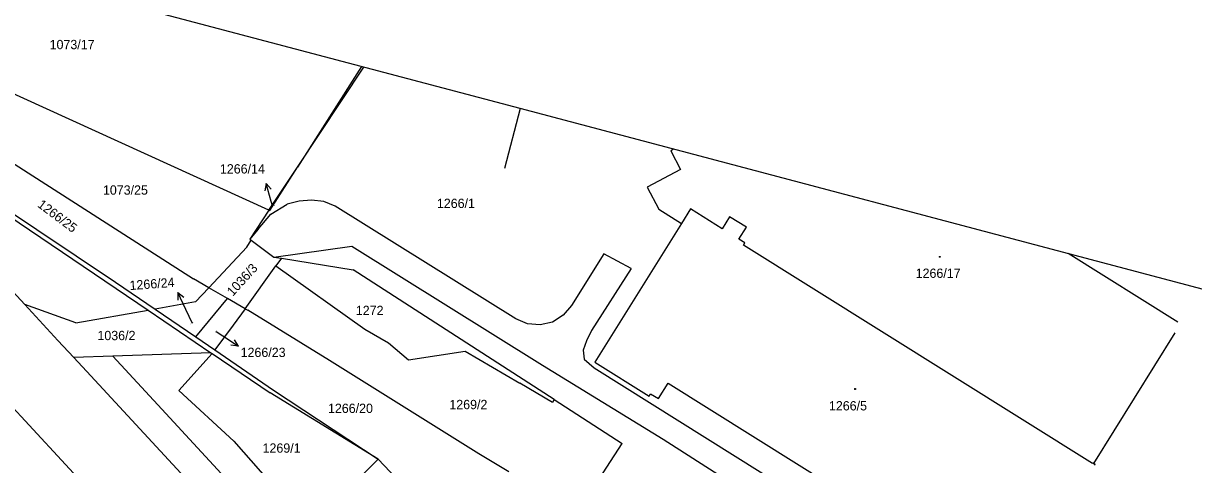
# Model space of a CAD drawing. Extents: x -805011 to -803920, y -1150790 to -1150234.
# Drawn here: x -804203.4 to -804014.7, y -1150506.7 to -1150435.6 of the extents above; entities that cross this region are included whole.
import ezdxf

# ---------------------------------------------------------------- set-up
doc = ezdxf.new("R2010")
doc.units = 0
for name, color, linetype in [('Default', 7, 'Continuous'), ('formát', 7, 'Continuous'), ('kn_celek - Cisla parcel pomocna', 7, 'Continuous'), ('kn_celek - Cisla pozemkovych parcel', 7, 'Continuous'), ('kn_celek - Cisla stavebnich parcel', 7, 'Continuous'), ('kn_celek - Hranice parcel', 7, 'Continuous'), ('kn_celek - Znacky budov', 7, 'Continuous')]:
    doc.layers.add(name, color=color, linetype=linetype)

# ---------------------------------------------------------------- blocks, each defined once
blk = doc.blocks.new('402')
at = {"layer": 'Default'}
for p, q in [((-0.8, 0.8), (0.7, 0.8)), ((-0.8, 0.8), (-0.8, -0.7)), ((0.7, 0.8), (0.7, -0.7)), ((0.7, -0.7), (-0.8, -0.7))]:
    blk.add_line(p, q, dxfattribs=at)
blk = doc.blocks.new('Z61')
at = {"layer": 'Default'}
for p, q in [((0, 0), (30, 0)), ((30, 0), (19.2, 5.3)), ((30, 0), (19.2, -5.3))]:
    blk.add_line(p, q, dxfattribs=at)

msp = doc.modelspace()

# ---------------------------------------------------------------- linework, layer by layer
at = {"layer": 'formát'}
for p, q in [((-804123.29, -1150449.3), (-804326.3, -1150395.58)), ((-804123.29, -1150449.3), (-804125.85, -1150458.97)), ((-803920.28, -1150503.02), (-804123.29, -1150449.3))]:
    msp.add_line(p, q, dxfattribs=at)
at = {"layer": 'kn_celek - Cisla parcel pomocna'}
for p, q in [((-804163.26, -1150464.96), (-804163.46, -1150464.27)), ((-804176.17, -1150483.96), (-804177.24, -1150481.68)), ((-804172.33, -1150485.22), (-804171.25, -1150485.95))]:
    msp.add_line(p, q, dxfattribs=at)
at = {"layer": 'kn_celek - Hranice parcel'}
for p, q in [((-804148.92, -1150442.52), (-804159.21, -1150458.72)), ((-804159.21, -1150458.72), (-804148.5, -1150442.63)), ((-804163.83, -1150465.67), (-804208.87, -1150445.2)), ((-804213.63, -1150452.62), (-804176.02, -1150476.77)), ((-804098.56, -1150455.85), (-804099.03, -1150456.1)), ((-804099.03, -1150456.1), (-804097.43, -1150459.12)), ((-804217.68, -1150458.55), (-804183.31, -1150481.83)), ((-804217.33, -1150458.04), (-804188.61, -1150477.27)), ((-804163.83, -1150465.67), (-804159.21, -1150458.72)), ((-804163.67, -1150465.74), (-804159.21, -1150458.72)), ((-804097.43, -1150459.12), (-804102.83, -1150461.99)), ((-804102.83, -1150461.99), (-804100.93, -1150465.54)), ((-804163.52, -1150466.35), (-804160.91, -1150464.71)), ((-804158.95, -1150464.21), (-804160.91, -1150464.71)), ((-804156.95, -1150464.08), (-804158.95, -1150464.21)), ((-804154.98, -1150464.3), (-804156.95, -1150464.08)), ((-804153.13, -1150465.01), (-804154.98, -1150464.3)), ((-804123.99, -1150483.22), (-804153.13, -1150465.01)), ((-804095.82, -1150465.49), (-804097.27, -1150467.82)), ((-804090.73, -1150468.69), (-804095.82, -1150465.49)), ((-804163.83, -1150465.67), (-804166.94, -1150470.34)), ((-804165.58, -1150468.76), (-804163.52, -1150466.35)), ((-804163.83, -1150465.67), (-804163.67, -1150465.74)), ((-804100.93, -1150465.54), (-804097.27, -1150467.82)), ((-804089.52, -1150466.74), (-804090.73, -1150468.69)), ((-804086.8, -1150468.43), (-804089.52, -1150466.74)), ((-804165.58, -1150468.76), (-804166.94, -1150470.34)), ((-804097.27, -1150467.82), (-804111.26, -1150490.2)), ((-804088.02, -1150470.38), (-804086.8, -1150468.43)), ((-804167.38, -1150471.65), (-804166.7, -1150470.52)), ((-804166.94, -1150470.34), (-804166.7, -1150470.52)), ((-804166.7, -1150470.52), (-804163.07, -1150473.24)), ((-804087.09, -1150470.96), (-804088.02, -1150470.38)), ((-804087.3, -1150471.3), (-804087.09, -1150470.96)), ((-804173.54, -1150478.2), (-804167.38, -1150471.65)), ((-804163.07, -1150473.24), (-804150.44, -1150471.47)), ((-804150.44, -1150471.47), (-804119.72, -1150490.69)), ((-804109.79, -1150472.7), (-804115.05, -1150481.07)), ((-804105.4, -1150475.1), (-804109.79, -1150472.7)), ((-804030.97, -1150506.52), (-804087.3, -1150471.3)), ((-804017.2, -1150483.73), (-804034.9, -1150472.69)), ((-804167.68, -1150481.57), (-804162.71, -1150474.67)), ((-804163.07, -1150473.24), (-804161.82, -1150473.44)), ((-804161.82, -1150473.44), (-804162.71, -1150474.67)), ((-804162.71, -1150474.67), (-804148.37, -1150484.88)), ((-804161.82, -1150473.44), (-804150.25, -1150475.3)), ((-804207.15, -1150476.64), (-804203.22, -1150480.89)), ((-804173.54, -1150478.2), (-804176.02, -1150476.77)), ((-804117.84, -1150496.2), (-804150.25, -1150475.3)), ((-804105.4, -1150475.1), (-804111.82, -1150485.07)), ((-804188.61, -1150477.27), (-804182.21, -1150481.63)), ((-804173.54, -1150478.2), (-804175.68, -1150480.47)), ((-804170.52, -1150479.94), (-804173.54, -1150478.2)), ((-804175.68, -1150480.47), (-804182.21, -1150481.63)), ((-804175.62, -1150486.13), (-804170.52, -1150479.94)), ((-804167.68, -1150481.57), (-804170.52, -1150479.94)), ((-804194.96, -1150483.87), (-804203.22, -1150480.89)), ((-804203.22, -1150480.89), (-804197.86, -1150486.67)), ((-804194.96, -1150483.87), (-804183.31, -1150481.83)), ((-804183.31, -1150481.83), (-804173.19, -1150488.68)), ((-804182.21, -1150481.63), (-804175.62, -1150486.13)), ((-804167.68, -1150481.57), (-804169.6, -1150484.24)), ((-804167.68, -1150481.57), (-804167.22, -1150481.83)), ((-804154.07, -1150489.93), (-804167.22, -1150481.83)), ((-804115.05, -1150481.07), (-804116.39, -1150482.61)), ((-804169.6, -1150484.24), (-804172.55, -1150488.22)), ((-804122.11, -1150484.02), (-804123.99, -1150483.22)), ((-804120.09, -1150484.19), (-804122.11, -1150484.02)), ((-804118.11, -1150483.74), (-804120.09, -1150484.19)), ((-804116.39, -1150482.61), (-804118.11, -1150483.74)), ((-804175.62, -1150486.13), (-804172.55, -1150488.22)), ((-804148.37, -1150484.88), (-804144.54, -1150487.07)), ((-804111.82, -1150485.07), (-804112.63, -1150486.75)), ((-804030.79, -1150506.51), (-804017.67, -1150485.48)), ((-804197.86, -1150486.67), (-804195.32, -1150489.41)), ((-804144.54, -1150487.07), (-804141.31, -1150489.79)), ((-804112.63, -1150486.75), (-804113.16, -1150488.23)), ((-804189.03, -1150489.2), (-804195.32, -1150489.41)), ((-804195.32, -1150489.41), (-804192.55, -1150492.4)), ((-804173.19, -1150488.68), (-804189.03, -1150489.2)), ((-804189.03, -1150489.2), (-804181.12, -1150497.76)), ((-804172.99, -1150488.81), (-804178.35, -1150494.75)), ((-804173.19, -1150488.68), (-804172.99, -1150488.81)), ((-804172.99, -1150488.81), (-804163.62, -1150495.16)), ((-804172.55, -1150488.22), (-804163.09, -1150494.68)), ((-804129.95, -1150504.97), (-804154.07, -1150489.93)), ((-804141.31, -1150489.79), (-804132.2, -1150488.43)), ((-804132.2, -1150488.43), (-804123.35, -1150493.57)), ((-804113.16, -1150488.23), (-804113.01, -1150489.73)), ((-804113.01, -1150489.73), (-804111.38, -1150491.09)), ((-804119.72, -1150490.69), (-804100.25, -1150502.6)), ((-804111.38, -1150491.09), (-804050.27, -1150529.35)), ((-804111.26, -1150490.2), (-804102.5, -1150495.66)), ((-804192.55, -1150492.4), (-804170.14, -1150516.6)), ((-804118.09, -1150496.67), (-804123.35, -1150493.57)), ((-804101.02, -1150496.07), (-804099.45, -1150493.57)), ((-804099.45, -1150493.57), (-804047.98, -1150525.74)), ((-804169.49, -1150502.94), (-804178.35, -1150494.75)), ((-804146.22, -1150505.84), (-804163.62, -1150495.16)), ((-804163.09, -1150494.68), (-804146.22, -1150505.84)), ((-804102.5, -1150495.66), (-804102.29, -1150495.28)), ((-804102.29, -1150495.28), (-804101.02, -1150496.07)), ((-804206.45, -1150496.09), (-804175.77, -1150529.26)), ((-804117.84, -1150496.2), (-804118.09, -1150496.67)), ((-804117.84, -1150496.2), (-804106.86, -1150503.28)), ((-804181.12, -1150497.76), (-804142.6, -1150539.45)), ((-804169.49, -1150502.94), (-804139.75, -1150536.68)), ((-804100.25, -1150502.6), (-804075.6, -1150518.36)), ((-804125.16, -1150507.9), (-804129.95, -1150504.97)), ((-804114.2, -1150514.6), (-804106.86, -1150503.28)), ((-804150, -1150509.6), (-804146.22, -1150505.84)), ((-804133.38, -1150519.26), (-804146.22, -1150505.84)), ((-804030.92, -1150506.44), (-804030.97, -1150506.52)), ((-804030.92, -1150506.44), (-804030.79, -1150506.51)), ((-804030.79, -1150506.51), (-804030.58, -1150506.63)), ((-804030.68, -1150506.78), (-804030.58, -1150506.63))]:
    msp.add_line(p, q, dxfattribs=at)

# ---------------------------------------------------------------- block references
at = {"layer": 'kn_celek - Cisla parcel pomocna'}
for p, xscale, yscale, rotation in [((-804163.46, -1150464.27), 0.1, 0.10000000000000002, 106.38963), ((-804177.24, -1150481.68), 0.1, 0.10000000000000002, 115.21755000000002), ((-804171.25, -1150485.95), 0.10000000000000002, 0.1, -34.09676999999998)]:
    msp.add_blockref('Z61', p, dxfattribs=dict(at, xscale=xscale, yscale=yscale, rotation=rotation))
at = {"layer": 'kn_celek - Znacky budov', "xscale": 0.1, "yscale": 0.10000000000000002}
for p in [(-804055.62, -1150473.21), (-804069.28, -1150494.51)]:
    msp.add_blockref('402', p, dxfattribs=at)

# ---------------------------------------------------------------- texts
at = {"layer": 'kn_celek - Cisla parcel pomocna'}
for s, p in [('1266/14', (-804171.74, -1150459.77)), ('1266/23', (-804168.4, -1150489.36))]:
    msp.add_text(s, height=1.5, dxfattribs=at).set_placement(p)
msp.add_text('1266/24', height=1.5, rotation=4.1151, dxfattribs=at).set_placement((-804186.26, -1150478.57))
at = {"layer": 'kn_celek - Cisla pozemkovych parcel'}
for s, height, p in [('1073/17', 1.5, (-804199.21, -1150439.72)), ('1073/25', 1.5, (-804190.61, -1150463.18)), ('1266/14', 0.1, (-804163.26, -1150464.93)), ('1266/1', 1.5, (-804136.74, -1150465.33)), ('1272', 1.5, (-804149.82, -1150482.6)), ('1036/2', 1.5, (-804191.5, -1150486.64)), ('1266/20', 1.5, (-804154.31, -1150498.38)), ('1269/2', 1.5, (-804134.73, -1150497.77)), ('1269/1', 1.5, (-804164.86, -1150504.79))]:
    msp.add_text(s, height=height, dxfattribs=at).set_placement(p)
for s, height, rotation, p in [('1266/25', 1.5, 323.0754, (-804201.29, -1150465.04)), ('1036/3', 1.5, 47.7, (-804169.67, -1150479.66)), ('1266/24', 0.1, 32.0278, (-804176.46, -1150484.1)), ('1266/23', 0.1, 51.9003, (-804172.55, -1150485.45))]:
    msp.add_text(s, height=height, rotation=rotation, dxfattribs=at).set_placement(p)
at = {"layer": 'kn_celek - Cisla stavebnich parcel'}
for s, p in [('1266/17', (-804059.51, -1150476.6)), ('1266/5', (-804073.5, -1150497.97))]:
    msp.add_text(s, height=1.5, dxfattribs=at).set_placement(p)

doc.saveas('drawing.dxf')
